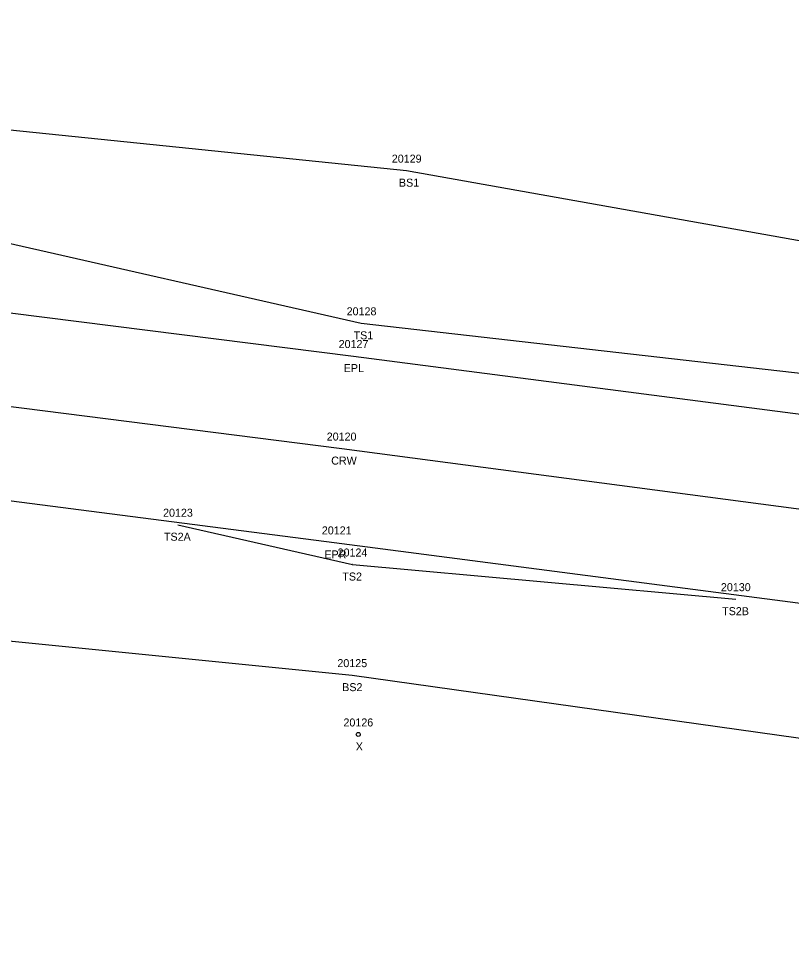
# Model space of a CAD drawing. Extents: x 2080935 to 2082049, y 730754 to 730962.
# Drawn here: x 2081721.9 to 2081818.5, y 730767 to 730882.9 of the extents above; entities that cross this region are included whole.
import ezdxf

# ---------------------------------------------------------------- set-up
doc = ezdxf.new("R2010")
doc.units = 0
for name, color, linetype in [('RD_DTM_BkLn1', 7, 'Continuous'), ('RD_DTM_BkLn2', 7, 'Continuous'), ('RD_EX_Road', 7, 'Continuous'), ('RD_EX_Road_txCode', 7, 'Continuous'), ('RD_Sketch8', 7, 'Continuous'), ('RD_SMD_Locator', 7, 'Continuous'), ('RD_SMD_Misc', 7, 'Continuous')]:
    doc.layers.add(name, color=color, linetype=linetype)

msp = doc.modelspace()

# ---------------------------------------------------------------- linework, layer by layer
at = {"layer": 'RD_DTM_BkLn1'}
msp.add_lwpolyline([(2081567.45, 730853.84), (2081663.53, 730841.7), (2081762.3, 730829.16), (2081864.76, 730815.62), (2081946.16, 730805.08), (2082043.01, 730792.22)], dxfattribs=at)
at = {"layer": 'RD_DTM_BkLn2'}
for points in [[(2081573.98, 730882.88), (2081669.72, 730874.22), (2081770.38, 730863.88), (2081871.58, 730845.86), (2081952.53, 730844.4), (2082047.2, 730823.74)], [(2081567.86, 730866.16), (2081571.2, 730868.83), (2081575.19, 730876.18), (2081667.17, 730866.99), (2081764.74, 730844.81), (2081867.48, 730833.13), (2081949.65, 730833.94), (2082043.99, 730810.42)], [(2081741.82, 730819.65), (2081763.62, 730814.68), (2081811.53, 730810.35)], [(2081562.68, 730817.88), (2081660.31, 730811.19), (2081763.58, 730800.86), (2081859.9, 730787.32), (2081942.25, 730773.23), (2082039.2, 730766.97)]]:
    msp.add_lwpolyline(points, dxfattribs=at)
at = {"layer": 'RD_EX_Road'}
for points in [[(2081567.45, 730853.84), (2081569.41, 730865.32), (2081665.09, 730853.16), (2081763.75, 730840.72), (2081866.15, 730827.41), (2081946.59, 730817.06), (2082042.99, 730804.46)], [(2081567.45, 730853.84), (2081564.7, 730842.25), (2081662.62, 730830.19), (2081761.36, 730817.44), (2081864.07, 730804.08), (2081944.33, 730793.7), (2082046, 730780.47)]]:
    msp.add_lwpolyline(points, dxfattribs=at)
at = {"layer": 'RD_SMD_Locator'}
for centre, radius in [((2081770.38, 730863.88), 0.001), ((2081764.74, 730844.81), 0.001), ((2081763.75, 730840.72), 0.001), ((2081762.3, 730829.16), 0.001), ((2081741.82, 730819.65), 0.001), ((2081761.36, 730817.44), 0.001), ((2081763.62, 730814.68), 0.001), ((2081811.53, 730810.35), 0.001), ((2081763.58, 730800.86), 0.001), ((2081764.36, 730793.45), 0.25)]:
    msp.add_circle(centre, radius, dxfattribs=at)

# ---------------------------------------------------------------- texts
at = {"layer": 'RD_EX_Road_txCode'}
for s, p in [('20127', (2081761.91, 730841.72)), ('EPL', (2081762.54, 730838.72)), ('20121', (2081759.81, 730818.44)), ('EPR', (2081760.13, 730815.44))]:
    msp.add_text(s, height=1, dxfattribs=at).set_placement(p)
at = {"layer": 'RD_Sketch8'}
for s, p in [('20126', (2081762.51, 730794.45)), ('X', (2081764.05, 730791.45))]:
    msp.add_text(s, height=1, dxfattribs=at).set_placement(p)
at = {"layer": 'RD_SMD_Misc'}
for s, p in [('20129', (2081768.55, 730864.88)), ('BS1', (2081769.44, 730861.88)), ('20128', (2081762.91, 730845.81)), ('TS1', (2081763.78, 730842.81)), ('20120', (2081760.42, 730830.16)), ('CRW', (2081760.98, 730827.16)), ('20123', (2081739.98, 730820.65)), ('TS2A', (2081740.09, 730817.65)), ('20124', (2081761.78, 730815.68)), ('TS2', (2081762.37, 730812.68)), ('20130', (2081809.66, 730811.35)), ('TS2B', (2081809.81, 730808.35)), ('20125', (2081761.75, 730801.86)), ('BS2', (2081762.35, 730798.86))]:
    msp.add_text(s, height=1, dxfattribs=at).set_placement(p)

doc.saveas('drawing.dxf')
